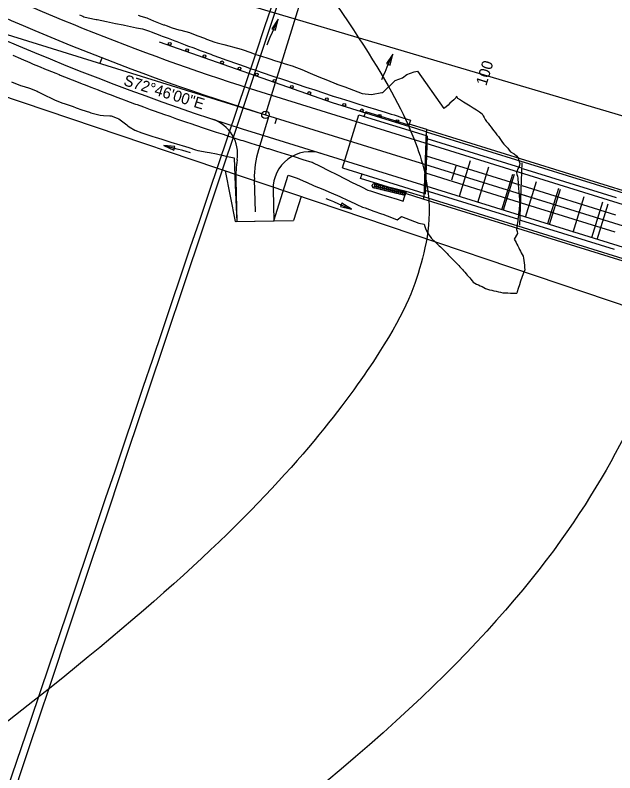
# Model space of a CAD drawing. Extents: x 1 to 1477871, y 1 to 1872901.
# Drawn here: x 1443500.7 to 1443824.9, y 1854698.4 to 1855107.8 of the extents above; entities that cross this region are included whole.
import ezdxf

# ---------------------------------------------------------------- set-up
doc = ezdxf.new("R2010")
doc.units = 0
for name, color, linetype in [('B_Centerline', 7, 'Continuous'), ('B_Concrete', 7, 'Continuous'), ('R_Drive', 7, 'Continuous'), ('R_Floodplain', 7, 'Continuous'), ('R_Horz Alg', 7, 'Continuous'), ('R_Horz Alg Annot', 7, 'Continuous'), ('R_No Plot', 7, 'Continuous'), ('R_Proposed Const Limits_Fill', 7, 'Continuous'), ('R_Proposed Const Limits_Hand', 7, 'Continuous'), ('R_Proposed Road_Lane', 7, 'Continuous'), ('R_Proposed Road_Shoulder', 7, 'Continuous'), ('R_ROW', 7, 'Continuous'), ('R_Steel', 7, 'Continuous'), ('R_Temp Easement', 7, 'Continuous'), ('R_Water', 7, 'Continuous')]:
    doc.layers.add(name, color=color, linetype=linetype)

msp = doc.modelspace()

# ---------------------------------------------------------------- linework, layer by layer
at = {"layer": 'B_Centerline'}
msp.add_line((1443774.65, 1855027.96), (1443773.34, 1854994.34), dxfattribs=at)
at = {"layer": 'B_Concrete'}
for p, q in [((1443689.43, 1855053.08), (1443690.2, 1855055.55)), ((1443713.56, 1855048.3), (1443690.2, 1855055.55)), ((1443677.68, 1855025.32), (1443686.57, 1855053.97)), ((1443686.57, 1855053.97), (1443722.86, 1855042.72)), ((1443713.76, 1855048.94), (1443713.39, 1855047.75)), ((1443722.94, 1855044.78), (1443713.39, 1855047.75)), ((1443723.31, 1855045.98), (1443713.76, 1855048.94)), ((1443722.94, 1855044.78), (1443721.57, 1855009.61)), ((1443723.31, 1855045.98), (1443722.94, 1855044.78)), ((1443722.94, 1855044.78), (1443877.99, 1854996.69)), ((1443723.31, 1855045.98), (1443878.36, 1854997.88)), ((1443677.68, 1855025.32), (1443721.65, 1855011.68)), ((1443687.46, 1855019.58), (1443688.22, 1855022.05)), ((1443711.85, 1855012.02), (1443687.46, 1855019.58)), ((1443712.02, 1855012.57), (1443711.65, 1855011.38)), ((1443721.2, 1855008.42), (1443711.65, 1855011.38)), ((1443721.57, 1855009.61), (1443712.02, 1855012.57)), ((1443721.57, 1855009.61), (1443721.2, 1855008.42)), ((1443876.62, 1854961.52), (1443721.57, 1855009.61)), ((1443876.25, 1854960.32), (1443721.2, 1855008.42))]:
    msp.add_line(p, q, dxfattribs=at)
at = {"layer": 'R_Drive'}
for p, q in [((1443620.01, 1855018.69), (1443620.59, 1854996.23)), ((1443640.15, 1855013.49), (1443640.58, 1854996.65)), ((1443620.59, 1854996.23), (1443640.58, 1854996.65))]:
    msp.add_line(p, q, dxfattribs=at)
for centre, radius, start, end in [((1443600.96, 1855032.65), 20, 351.0734, 71.6392), ((1443660.14, 1855014.01), 20, 72.7667, 181.478), ((1443679.99, 1855020.23), 60, 171.0734, 181.478)]:
    msp.add_arc(centre, radius, start, end, dxfattribs=at)
at = {"layer": 'R_Floodplain'}
for points in [[(1444534.23, 1857777.84), (1444398.78, 1857609.12), (1444367.89, 1857131.47), (1444306.1, 1856808.28), (1444134.95, 1856378.26), (1444024.62, 1856227.92), (1443837.91, 1855964.82), (1443664.53, 1855852.06), (1443479.03, 1855867.82), (1443335.96, 1855886.01), (1443298.37, 1855854.49), (1443356.57, 1855756.28), (1443606.51, 1855482.27), (1443757.19, 1855307.33), (1443863.11, 1855113.58), (1443878.59, 1855007.91), (1443849.87, 1854910.07), (1443760.66, 1854753.08), (1443429.28, 1854512.04), (1443240.87, 1854371.16), (1443115.26, 1854254.04), (1443060.94, 1853889.1), (1443099.99, 1853680.31), (1443032.09, 1853386.66), (1443001.54, 1853198.25), (1444534.23, 1857777.84), (1443001.54, 1853198.25)], [(1442151.14, 1856970.74), (1442271.17, 1856854.35), (1442333.01, 1856625.2), (1442433.64, 1856208.12), (1442553.67, 1856042.02), (1442997.42, 1855782.56), (1443193.84, 1855637.06), (1443334.48, 1855500.06), (1443473.91, 1855372.75), (1443683.66, 1855109.66), (1443730.06, 1855020.65), (1443721.27, 1854972.23), (1443705.74, 1854932.59), (1443621.79, 1854821.68), (1443387.16, 1854639.56), (1443131.33, 1854479.52), (1443010.09, 1854397.07), (1442954.32, 1854286.74), (1442894.91, 1853873.3), (1442881.57, 1853521.69), (1442881.57, 1853348.32), (1442151.14, 1856970.74), (1442881.57, 1853348.32)]]:
    msp.add_open_spline(points, degree=3, dxfattribs=at)
at = {"layer": 'R_Horz Alg'}
for p, q in [((1443635.98, 1855053.96), (1443893.97, 1854973.93)), ((1443635.98, 1855053.96), (1443893.97, 1854973.93)), ((1443774.07, 1855011.13), (1443799.85, 1855003.13))]:
    msp.add_line(p, q, dxfattribs=at)
msp.add_arc((1444035.38, 1856341.58), 1348.14, 233.78664, 252.76667, dxfattribs=at)
msp.add_arc((1444035.38, 1856341.58), 1348.14, 233.78664, 252.76667, dxfattribs=at)
at = {"layer": 'R_Horz Alg Annot'}
msp.add_line((1443420.74, 1855120.73), (1443635.98, 1855053.96), dxfattribs=at)
for points in [[(1443635.98, 1855053.96), (1443671.53, 1855168.57)], [(1443546.62, 1855081.94), (1443547.71, 1855084.73)], [(1443641.3, 1855049.17), (1443642.19, 1855052.03)], [(1443738.88, 1855026.23), (1443736.51, 1855018.59)]]:
    msp.add_lwpolyline(points, dxfattribs=at)
msp.add_circle((1443635.98, 1855053.96), 2, dxfattribs=at)
at = {"layer": 'R_No Plot'}
for p, q in [((1443637.91, 1855053.36), (1443632.23, 1855035.05)), ((1443723.5, 1855042.6), (1443722.27, 1855011.08)), ((1443774.06, 1855025.26), (1443723.44, 1855040.97)), ((1443773.7, 1855015.95), (1443723.08, 1855031.66)), ((1443746.64, 1855028.98), (1443740.68, 1855009.75)), ((1443773.33, 1855006.64), (1443722.71, 1855022.35)), ((1443750.85, 1855006.59), (1443756.82, 1855025.82)), ((1443775.01, 1855024.97), (1443825.63, 1855009.27)), ((1443630, 1855018.94), (1443630.45, 1855001.56)), ((1443763.75, 1855002.59), (1443769.71, 1855021.83)), ((1443770.53, 1855021.61), (1443764.55, 1855002.34)), ((1443776.64, 1854998.59), (1443782.61, 1855017.83)), ((1443774.65, 1855015.66), (1443825.27, 1854999.96)), ((1443794.41, 1855014.2), (1443788.43, 1854994.94)), ((1443789.53, 1854994.59), (1443795.5, 1855013.83)), ((1443772.97, 1854997.33), (1443722.35, 1855013.03)), ((1443802.43, 1854990.59), (1443808.39, 1855009.83)), ((1443774.29, 1855006.35), (1443824.91, 1854990.64)), ((1443818.27, 1855006.76), (1443812.31, 1854987.53)), ((1443815.32, 1854986.59), (1443821.29, 1855005.83)), ((1443773.92, 1854997.04), (1443824.55, 1854981.33))]:
    msp.add_line(p, q, dxfattribs=at)
msp.add_arc((1443679.99, 1855020.23), 50, 162.7667, 181.478, dxfattribs=at)
at = {"layer": 'R_Proposed Const Limits_Fill'}
for points in [[(1443567.17, 1855107.83), (1443568.67, 1855107.31), (1443571.8, 1855106.24), (1443572.29, 1855106.07), (1443575.48, 1855104.72), (1443576.32, 1855104.36), (1443580.9, 1855102.63), (1443581.39, 1855102.46), (1443582.29, 1855102.14), (1443585.51, 1855100.98), (1443589.23, 1855099.89), (1443590.22, 1855099.63), (1443594.95, 1855098.32), (1443596.23, 1855097.83), (1443599.53, 1855096.58), (1443603.05, 1855095.27), (1443604.11, 1855094.86), (1443608.68, 1855093.11), (1443609.89, 1855092.78), (1443613.45, 1855091.96), (1443616.99, 1855091.02), (1443618.19, 1855090.71), (1443622.91, 1855089.38), (1443623.98, 1855088.99), (1443627.5, 1855087.71), (1443630.85, 1855086.57), (1443632.14, 1855086.15), (1443636.79, 1855084.64), (1443637.78, 1855084.33), (1443641.45, 1855083.15), (1443644.71, 1855082.12), (1443646.14, 1855081.67), (1443650.91, 1855080.17), (1443651.42, 1855080.01), (1443655.6, 1855078.41), (1443660.21, 1855076.39), (1443664.86, 1855074.49), (1443669.51, 1855072.6), (1443674.16, 1855070.74), (1443674.53, 1855070.6), (1443674.66, 1855070.55), (1443678.85, 1855068.97), (1443683.53, 1855067.18), (1443688.21, 1855065.38), (1443693.31, 1855064.94), (1443698.86, 1855065.96), (1443699.45, 1855066.07), (1443706.11, 1855072.46), (1443710.12, 1855073.95), (1443712.36, 1855075.75), (1443716.45, 1855077.06), (1443718.2, 1855077.57)], [(1443718.2, 1855077.57), (1443732.52, 1855057.29)], [(1443498.8, 1855071.74), (1443503.54, 1855069.82), (1443505.48, 1855069.25), (1443508.48, 1855068.38), (1443512.64, 1855066.66), (1443513.18, 1855066.39), (1443517.76, 1855064.09), (1443519.47, 1855063.25), (1443520.09, 1855062.94), (1443522.37, 1855061.83), (1443526.46, 1855060.24), (1443527.14, 1855060), (1443531.98, 1855058.33), (1443533.66, 1855057.76), (1443536.82, 1855056.68), (1443540.87, 1855055.3), (1443541.66, 1855055.03), (1443546.65, 1855053.76), (1443548.37, 1855053.63), (1443551.95, 1855053.36), (1443552.52, 1855053.32), (1443555.91, 1855052.09), (1443556.77, 1855051.67), (1443561.02, 1855048.44), (1443561.47, 1855048.09), (1443562.3, 1855047.44), (1443565.43, 1855045.6), (1443569.22, 1855044.2), (1443570.24, 1855043.87), (1443575.1, 1855042.27), (1443576.45, 1855041.83), (1443579.96, 1855040.69), (1443583.71, 1855039.53), (1443584.85, 1855039.18), (1443589.74, 1855037.69), (1443590.99, 1855037.31), (1443594.63, 1855036.2), (1443598.26, 1855035.06), (1443599.51, 1855034.69), (1443604.57, 1855033.71), (1443605.75, 1855033.49), (1443609.63, 1855032.76), (1443613.25, 1855031.97), (1443614.64, 1855031.67), (1443619.11, 1855030.72)], [(1443619.11, 1855030.72), (1443619.6, 1855015.89), (1443620.59, 1854996.23), (1443640.58, 1854996.65), (1443648.37, 1855021.36)], [(1443648.37, 1855021.36), (1443648.8, 1855021.21), (1443653.08, 1855019.65), (1443657.71, 1855017.69), (1443658.07, 1855017.54), (1443658.2, 1855017.48), (1443662.3, 1855015.62), (1443666.96, 1855013.75), (1443671.6, 1855011.85), (1443676.18, 1855009.75), (1443680.75, 1855007.6), (1443681.25, 1855007.4), (1443685.34, 1855005.52), (1443688.46, 1855004.12), (1443689.98, 1855003.59), (1443694.69, 1855001.89), (1443698.72, 1855000.45), (1443699.4, 1855000.21), (1443704.12, 1854998.53), (1443707.26, 1854997.23), (1443709.49, 1854998.97), (1443714.17, 1854997.18), (1443718.85, 1854995.39), (1443721.81, 1854994.9)]]:
    msp.add_lwpolyline(points, dxfattribs=at)
at = {"layer": 'R_Proposed Const Limits_Hand'}
for points in [[(1443739.29, 1855064.03), (1443738.85, 1855063.05), (1443737.83, 1855062.09), (1443736.81, 1855061.12), (1443735.78, 1855060.16), (1443734.76, 1855059.2), (1443733.65, 1855058.25), (1443732.52, 1855057.29)], [(1443739.29, 1855064.03), (1443739.87, 1855063.01), (1443741.4, 1855061.95), (1443743.04, 1855060.88), (1443744.86, 1855059.81), (1443746.63, 1855058.74), (1443748.33, 1855057.67), (1443750.04, 1855056.61), (1443751.74, 1855055.54), (1443753.2, 1855054.48), (1443753.73, 1855053.46), (1443754.26, 1855052.44), (1443754.79, 1855051.42), (1443755.58, 1855050.38), (1443756.38, 1855049.35), (1443757.17, 1855048.32), (1443757.97, 1855047.29), (1443758.76, 1855046.26), (1443759.56, 1855045.23), (1443760.35, 1855044.19), (1443761.15, 1855043.16), (1443761.94, 1855042.13), (1443762.74, 1855041.1), (1443763.53, 1855040.07), (1443764.23, 1855039.04), (1443764.92, 1855038.01), (1443765.95, 1855036.97), (1443766.97, 1855035.93), (1443767.85, 1855034.9), (1443768.48, 1855033.87), (1443770.45, 1855032.79), (1443771.81, 1855031.74), (1443772.55, 1855030.71), (1443772.86, 1855029.7), (1443773.16, 1855028.68), (1443773.46, 1855027.67), (1443773.44, 1855026.67), (1443772.99, 1855025.69), (1443772.54, 1855024.7), (1443772.1, 1855023.72), (1443771.65, 1855022.74), (1443771.88, 1855021.73), (1443772.3, 1855020.71), (1443772.38, 1855019.71), (1443772.47, 1855018.7), (1443772.55, 1855017.7), (1443772.64, 1855016.69), (1443772.72, 1855015.69), (1443772.81, 1855014.69), (1443772.9, 1855013.68), (1443772.98, 1855012.68), (1443773.07, 1855011.67), (1443773.15, 1855010.67), (1443773.24, 1855009.67), (1443773.33, 1855008.66), (1443773.41, 1855007.66), (1443773.5, 1855006.65), (1443773.41, 1855005.66), (1443773.3, 1855004.66), (1443773.2, 1855003.66), (1443773.09, 1855002.67), (1443772.98, 1855001.67), (1443772.88, 1855000.67), (1443772.77, 1854999.68), (1443772.66, 1854998.68), (1443772.53, 1854997.68), (1443772.39, 1854996.69), (1443772.25, 1854995.69), (1443772.11, 1854994.7), (1443771.94, 1854993.51), (1443771.75, 1854991.97), (1443772.03, 1854990.86), (1443772.31, 1854989.76), (1443770.53, 1854986.75), (1443771.02, 1854985.84), (1443771.49, 1854984.92), (1443771.97, 1854984), (1443772.44, 1854983.07), (1443772.92, 1854982.15), (1443773.39, 1854981.23), (1443773.87, 1854980.31), (1443774.34, 1854979.38), (1443774.82, 1854978.46), (1443775.3, 1854977.54), (1443775.6, 1854976.46), (1443775.74, 1854975.22), (1443775.87, 1854973.99), (1443776.01, 1854972.75), (1443776.15, 1854971.52), (1443776.21, 1854970.21), (1443775.4, 1854968.1), (1443774.58, 1854965.98), (1443773.87, 1854963.97), (1443773.27, 1854962.05), (1443772.67, 1854960.13), (1443772.07, 1854958.21), (1443771.85, 1854957.52)], [(1443721.81, 1854994.9), (1443722.14, 1854993.64), (1443722.57, 1854992.43), (1443723.1, 1854991.29), (1443723.71, 1854990.2), (1443724.31, 1854989.14), (1443724.99, 1854988.13), (1443725.74, 1854987.19), (1443726.58, 1854986.33), (1443726.97, 1854985.96), (1443727.7, 1854985.28), (1443728.43, 1854984.59), (1443729.16, 1854983.9), (1443729.89, 1854983.21), (1443730.61, 1854982.53), (1443731.34, 1854981.84), (1443732.06, 1854981.14), (1443732.77, 1854980.44), (1443733.48, 1854979.72), (1443734.18, 1854979.01), (1443734.88, 1854978.3), (1443735.58, 1854977.59), (1443736.28, 1854976.87), (1443736.99, 1854976.16), (1443737.69, 1854975.45), (1443738.39, 1854974.73), (1443739.09, 1854974.02), (1443739.79, 1854973.31), (1443740.5, 1854972.6), (1443741.19, 1854971.88), (1443741.85, 1854971.12), (1443742.5, 1854970.36), (1443743.16, 1854969.61), (1443743.81, 1854968.85), (1443744.47, 1854968.09), (1443745.12, 1854967.34), (1443745.78, 1854966.58), (1443746.43, 1854965.82), (1443747.08, 1854965.07), (1443747.74, 1854964.31), (1443748.39, 1854963.56), (1443749.23, 1854962.97), (1443750.2, 1854962.5), (1443751.17, 1854962.04), (1443752.14, 1854961.57), (1443753.11, 1854961.11), (1443754.08, 1854960.64), (1443754.97, 1854960.1), (1443756.03, 1854959.72), (1443757.21, 1854959.45), (1443758.38, 1854959.17), (1443759.56, 1854958.9), (1443760.74, 1854958.63), (1443761.92, 1854958.36), (1443763.1, 1854958.08), (1443764.28, 1854957.81), (1443765.63, 1854957.7), (1443767.06, 1854957.66), (1443768.48, 1854957.62), (1443769.91, 1854957.58), (1443771.34, 1854957.54), (1443771.85, 1854957.52)]]:
    msp.add_lwpolyline(points, dxfattribs=at)
at = {"layer": 'R_Proposed Road_Lane'}
for p, q in [((1443639.24, 1855064.47), (1443897.23, 1854984.44)), ((1443632.72, 1855043.45), (1443890.71, 1854963.43))]:
    msp.add_line(p, q, dxfattribs=at)
for radius, start in [(1359.14, 240.29296), (1337.14, 244.54295)]:
    msp.add_arc((1444035.38, 1856341.58), radius, start, 252.76667, dxfattribs=at)
at = {"layer": 'R_Proposed Road_Shoulder'}
for points in [[(1443535.5, 1855107.86), (1443537.2, 1855107.18), (1443537.82, 1855106.93), (1443540.23, 1855106.4), (1443544.44, 1855105.49), (1443545.12, 1855105.35), (1443550.02, 1855104.31), (1443551.72, 1855103.96), (1443554.91, 1855103.3), (1443559, 1855102.46), (1443559.81, 1855102.3), (1443564.7, 1855101.33), (1443566.29, 1855101.01), (1443569.6, 1855100.37), (1443570.12, 1855100.27), (1443573.37, 1855099.05), (1443574.23, 1855098.73), (1443578.85, 1855097.03), (1443579.34, 1855096.85), (1443580.24, 1855096.5), (1443583.44, 1855095.26), (1443587.07, 1855093.87), (1443588.03, 1855093.5), (1443592.63, 1855091.76), (1443593.91, 1855091.27), (1443597.23, 1855090.03), (1443600.77, 1855088.71), (1443601.84, 1855088.32), (1443606.46, 1855086.62), (1443607.65, 1855086.19), (1443611.09, 1855084.95), (1443614.54, 1855083.71), (1443615.72, 1855083.29), (1443620.36, 1855081.64), (1443621.44, 1855081.26), (1443625, 1855080.02), (1443628.36, 1855078.85), (1443629.65, 1855078.41), (1443634.31, 1855076.82), (1443635.3, 1855076.48), (1443638.97, 1855075.24), (1443642.24, 1855074.15), (1443643.67, 1855073.68), (1443648.41, 1855072.1), (1443648.91, 1855071.93), (1443653.16, 1855070.53), (1443657.9, 1855068.95), (1443662.65, 1855067.37), (1443667.4, 1855065.79), (1443672.14, 1855064.22), (1443672.51, 1855064.09), (1443672.64, 1855064.05), (1443676.91, 1855062.73), (1443681.69, 1855061.25), (1443686.46, 1855059.76), (1443691.24, 1855058.28), (1443696.02, 1855056.8), (1443696.52, 1855056.64), (1443700.79, 1855055.32), (1443704.03, 1855054.32), (1443705.57, 1855053.84), (1443710.34, 1855052.36), (1443714.43, 1855051.09), (1443713.39, 1855047.75)], [(1443499.36, 1855086.08), (1443503.58, 1855084.28), (1443504.02, 1855084.1), (1443508.69, 1855082.13), (1443510.52, 1855081.37), (1443513.36, 1855080.19), (1443517.49, 1855078.49), (1443518.04, 1855078.26), (1443522.73, 1855076.35), (1443524.47, 1855075.65), (1443525.11, 1855075.39), (1443527.43, 1855074.46), (1443531.47, 1855072.85), (1443532.13, 1855072.58), (1443536.84, 1855070.73), (1443538.48, 1855070.08), (1443541.56, 1855068.89), (1443545.51, 1855067.36), (1443546.28, 1855067.06), (1443551.01, 1855065.26), (1443552.55, 1855064.67), (1443555.75, 1855063.47), (1443556.25, 1855063.28), (1443559.61, 1855062.03), (1443560.49, 1855061.7), (1443565.24, 1855059.95), (1443565.75, 1855059.76), (1443566.68, 1855059.42), (1443570, 1855058.21), (1443573.77, 1855056.85), (1443574.76, 1855056.5), (1443579.53, 1855054.8), (1443580.87, 1855054.32), (1443584.31, 1855053.11), (1443587.98, 1855051.83), (1443589.09, 1855051.45), (1443593.88, 1855049.8), (1443595.11, 1855049.38), (1443598.67, 1855048.18), (1443602.25, 1855046.97), (1443603.47, 1855046.56), (1443608.28, 1855044.97), (1443609.4, 1855044.6), (1443613.09, 1855043.4), (1443616.57, 1855042.27), (1443617.91, 1855041.84), (1443622.73, 1855040.3), (1443623.75, 1855039.98), (1443627.56, 1855038.78), (1443630.94, 1855037.72), (1443632.38, 1855037.28), (1443637.15, 1855035.8), (1443637.66, 1855035.64), (1443641.93, 1855034.32), (1443646.7, 1855032.84), (1443651.48, 1855031.35), (1443656.25, 1855029.87), (1443661.03, 1855028.39), (1443661.4, 1855028.28), (1443661.53, 1855028.21), (1443665.58, 1855026.18), (1443670.1, 1855023.9), (1443674.63, 1855021.62), (1443679.16, 1855019.34), (1443683.69, 1855017.07), (1443684.17, 1855016.83), (1443688.22, 1855014.79), (1443691.29, 1855013.25), (1443692.83, 1855012.77), (1443697.6, 1855011.29), (1443701.69, 1855010.02), (1443702.38, 1855009.81), (1443707.15, 1855008.33), (1443710.39, 1855007.32), (1443712.02, 1855012.57)]]:
    msp.add_lwpolyline(points, dxfattribs=at)
at = {"layer": 'R_ROW'}
for p, q in [((1443565.8, 1855131.35), (1443949.34, 1855017.73)), ((1443436.56, 1855083.7), (1443895.27, 1854928.7))]:
    msp.add_line(p, q, dxfattribs=at)
at = {"layer": 'R_Steel'}
for p, q in [((1443693.68, 1855015.6), (1443693.73, 1855015.85)), ((1443711.35, 1855010.42), (1443694.42, 1855014.4)), ((1443712.02, 1855012.57), (1443694.94, 1855016.59)), ((1443712.02, 1855012.57), (1443711.35, 1855010.42))]:
    msp.add_line(p, q, dxfattribs=at)
msp.add_lwpolyline([(1443578.64, 1855093.38), (1443672.09, 1855060.56), (1443713.9, 1855047.59)], dxfattribs=at)
for centre, radius in [((1443584.24, 1855092.21), 0.75), ((1443593.67, 1855088.89), 0.75), ((1443603.11, 1855085.58), 0.75), ((1443612.54, 1855082.27), 0.75), ((1443621.98, 1855078.95), 0.75), ((1443631.41, 1855075.64), 0.75), ((1443640.85, 1855072.33), 0.75), ((1443650.28, 1855069.01), 0.75), ((1443659.72, 1855065.7), 0.75), ((1443669.15, 1855062.38), 0.75), ((1443678.64, 1855059.31), 0.75), ((1443688.19, 1855056.35), 0.75), ((1443697.74, 1855053.39), 0.75), ((1443707.29, 1855050.42), 0.75), ((1443695.27, 1855014.78), 0.563), ((1443695.53, 1855015.87), 0.563), ((1443696.37, 1855014.52), 0.563), ((1443696.62, 1855015.62), 0.563), ((1443697.46, 1855014.27), 0.563), ((1443697.72, 1855015.36), 0.563), ((1443698.56, 1855014.01), 0.563), ((1443698.81, 1855015.1), 0.563), ((1443699.65, 1855013.75), 0.563), ((1443699.91, 1855014.84), 0.563), ((1443700.75, 1855013.49), 0.563), ((1443701.01, 1855014.59), 0.563), ((1443701.84, 1855013.23), 0.563), ((1443702.1, 1855014.33), 0.563), ((1443703.2, 1855014.07), 0.563), ((1443704.29, 1855013.81), 0.563), ((1443705.39, 1855013.56), 0.563), ((1443706.48, 1855013.3), 0.563), ((1443702.94, 1855012.98), 0.563), ((1443704.03, 1855012.72), 0.563), ((1443705.13, 1855012.46), 0.563), ((1443706.22, 1855012.2), 0.563), ((1443707.32, 1855011.95), 0.563), ((1443707.58, 1855013.04), 0.563), ((1443708.41, 1855011.69), 0.563), ((1443708.67, 1855012.78), 0.563), ((1443709.51, 1855011.43), 0.563), ((1443709.77, 1855012.53), 0.563), ((1443710.6, 1855011.17), 0.563), ((1443710.6, 1855011.17), 0.563), ((1443710.86, 1855012.27), 0.563), ((1443710.86, 1855012.27), 0.563)]:
    msp.add_circle(centre, radius, dxfattribs=at)
for centre, start, end in [((1443694.65, 1855015.38), 166.7648, 256.7648), ((1443694.71, 1855015.62), 76.7648, 166.7648)]:
    msp.add_arc(centre, 1, start, end, dxfattribs=at)
at = {"layer": 'R_Temp Easement'}
for p, q in [((1443614.23, 1855023.67), (1443619.64, 1854996.21)), ((1443655.26, 1855009.8), (1443651.25, 1854996.87)), ((1443619.64, 1854996.21), (1443651.25, 1854996.87))]:
    msp.add_line(p, q, dxfattribs=at)
at = {"layer": 'R_Water'}
for p, q in [((1443642.82, 1855105.55), (1443639.48, 1855100.45)), ((1443641.42, 1855099.62), (1443642.82, 1855105.55)), ((1443639.48, 1855100.45), (1443641.42, 1855099.62)), ((1443704.83, 1855086.73), (1443701.49, 1855081.64)), ((1443703.43, 1855080.8), (1443704.83, 1855086.73)), ((1443701.49, 1855081.64), (1443703.43, 1855080.8)), ((1443581.03, 1855037.3), (1443586.55, 1855034.74)), ((1443587.1, 1855036.78), (1443581.03, 1855037.3)), ((1443586.55, 1855034.74), (1443587.1, 1855036.78)), ((1443677.38, 1855006.26), (1443676.56, 1855004.31)), ((1443682.51, 1855002.97), (1443677.38, 1855006.26)), ((1443676.56, 1855004.31), (1443682.51, 1855002.97))]:
    msp.add_line(p, q, dxfattribs=at)
for points in [[(1443636.9, 1855091.76), (1443637.89, 1855094.08), (1443638.64, 1855095.81), (1443639.86, 1855098.66), (1443641.83, 1855103.24), (1443642.82, 1855105.55)], [(1443698.91, 1855072.95), (1443699.91, 1855075.26), (1443700.65, 1855077), (1443701.87, 1855079.84), (1443703.84, 1855084.42), (1443704.83, 1855086.73)], [(1443595.52, 1855033.46), (1443593.09, 1855034.1), (1443591.27, 1855034.58), (1443588.27, 1855035.38), (1443583.46, 1855036.66), (1443581.03, 1855037.3)], [(1443668.66, 1855008.75), (1443670.99, 1855007.78), (1443672.73, 1855007.05), (1443675.59, 1855005.86), (1443680.19, 1855003.94), (1443682.51, 1855002.97)]]:
    msp.add_lwpolyline(points, dxfattribs=at)

# ---------------------------------------------------------------- texts
at = {"layer": 'R_Horz Alg Annot'}
for s, rotation, p in [('100', 72.7667, (1443755.38, 1855069.27)), ('S72%%d46\'00"E', 342.7667, (1443558.85, 1855070.05))]:
    msp.add_text(s, height=6, rotation=rotation, dxfattribs=at).set_placement(p)

doc.saveas('drawing.dxf')
